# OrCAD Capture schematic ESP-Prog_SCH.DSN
size A3; title: ESP32-PROG-BRD_V2; rev: 1.0
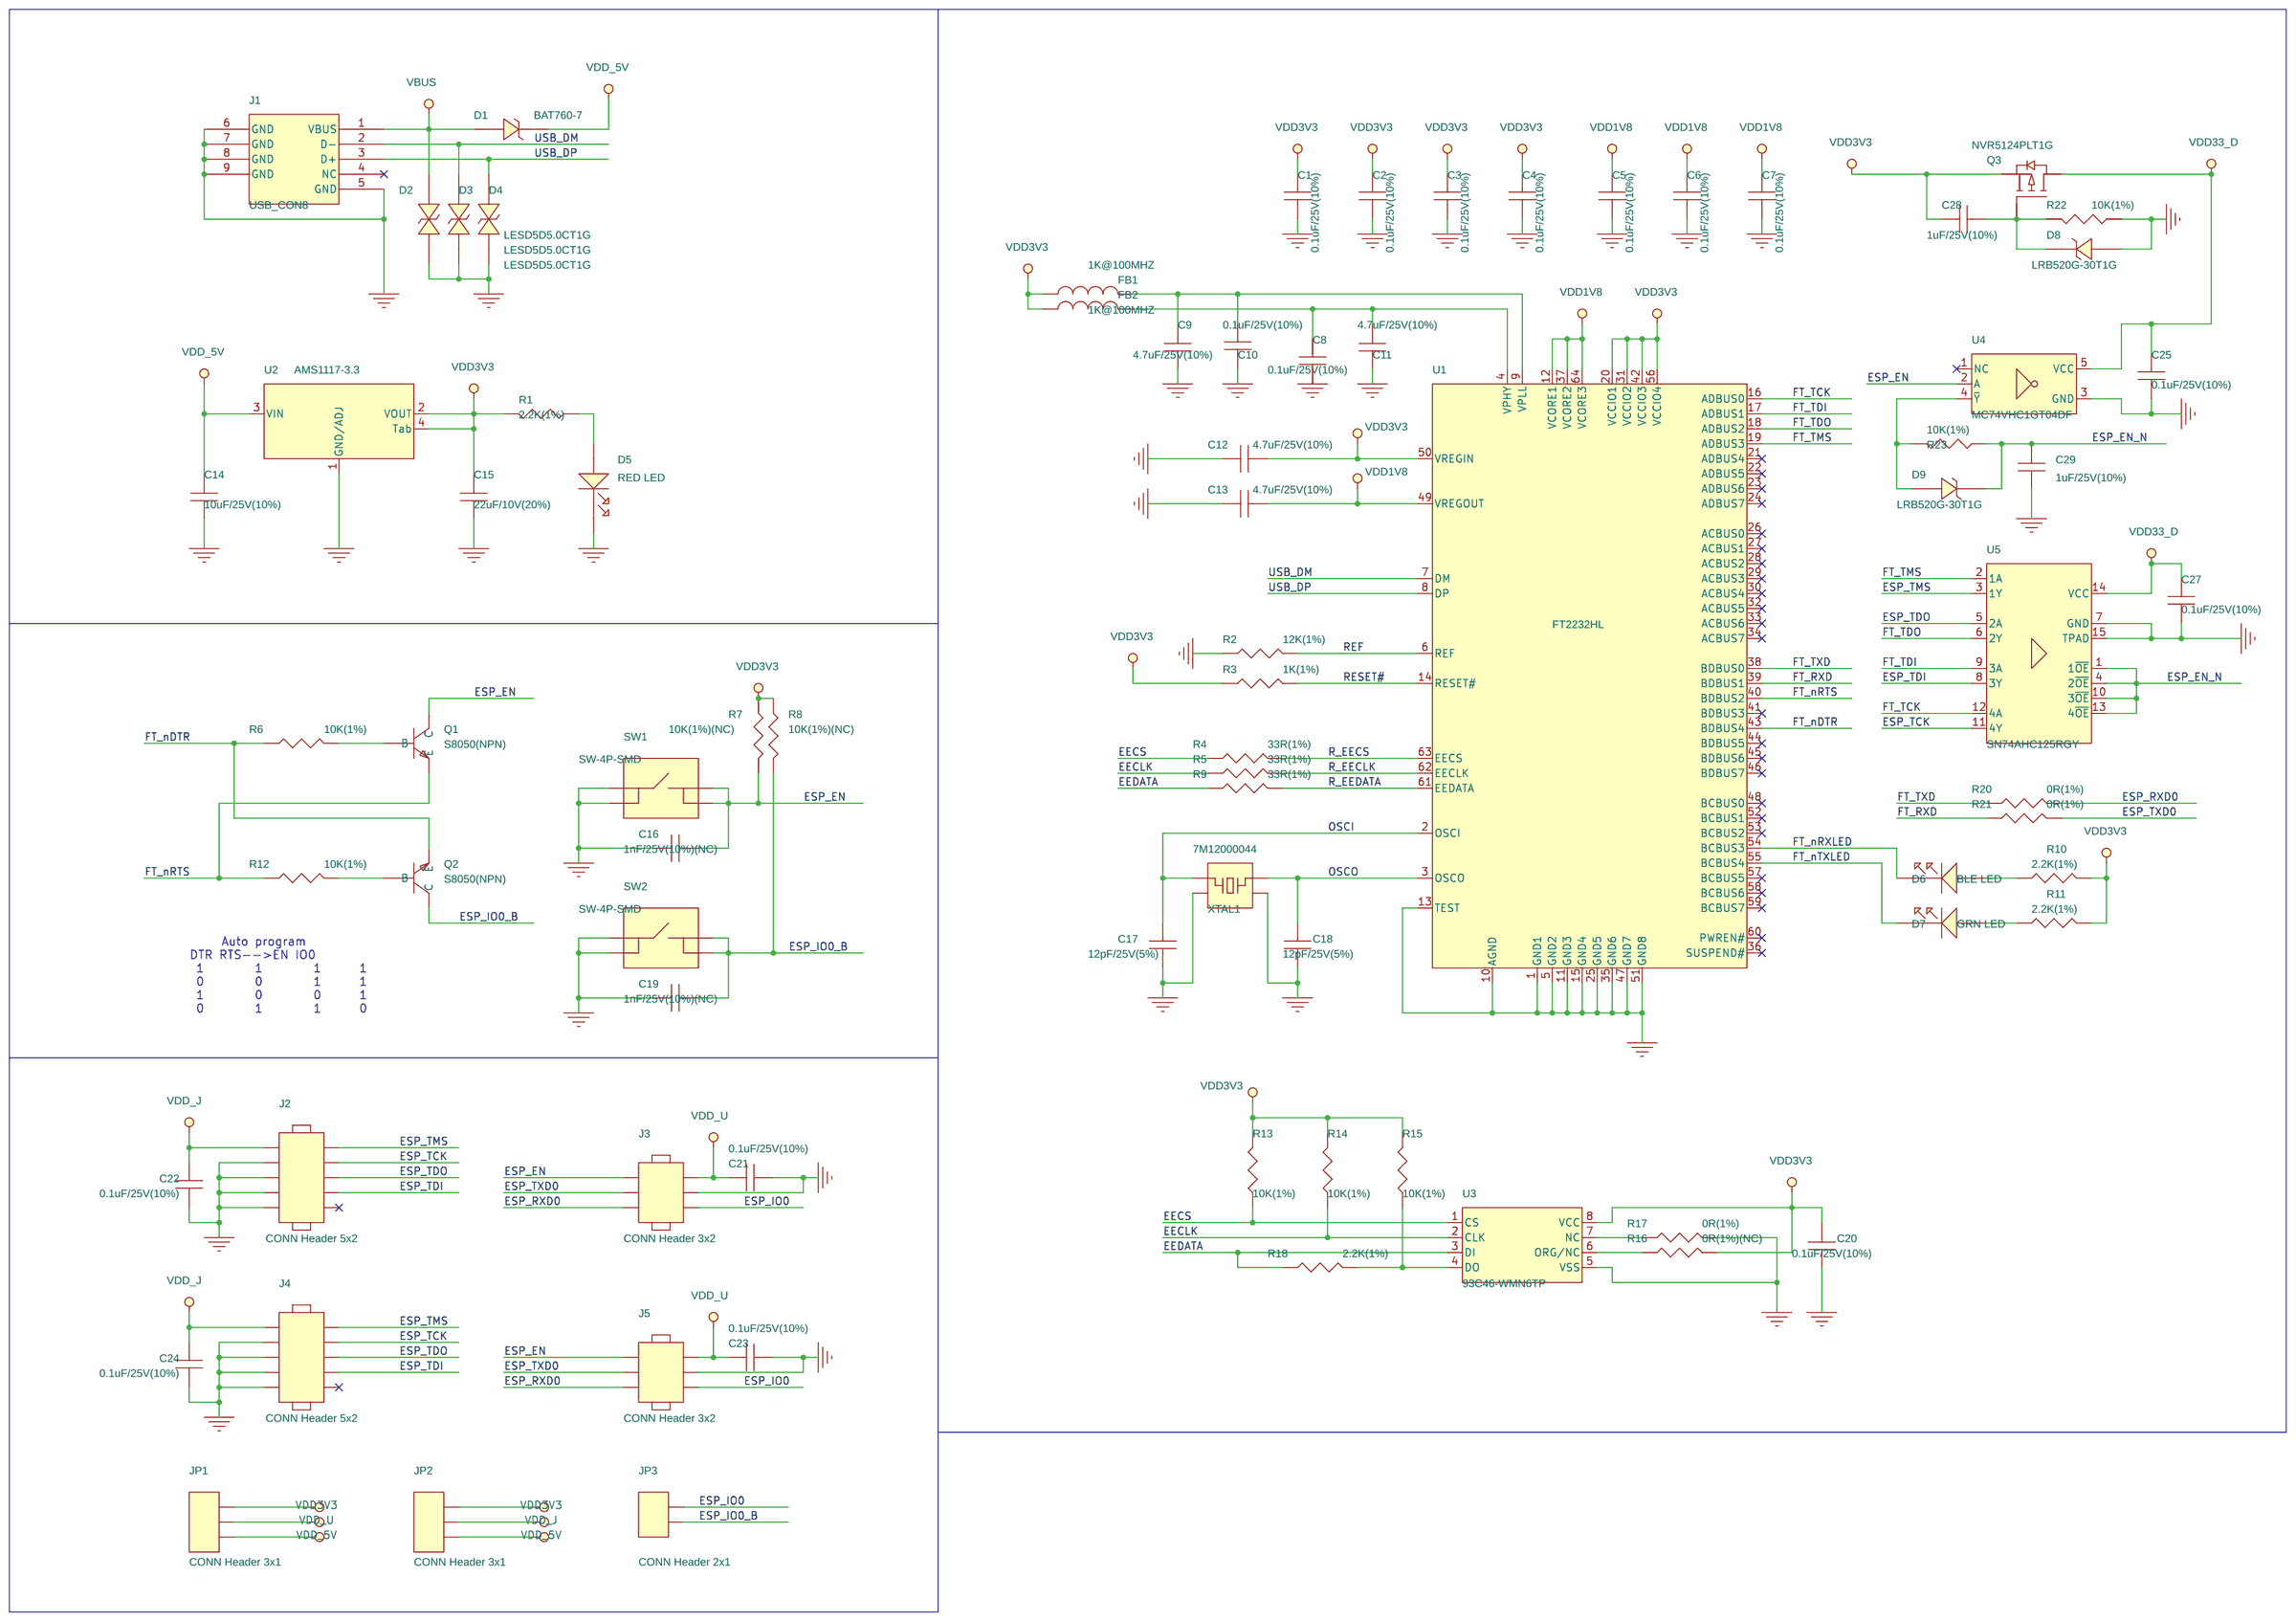
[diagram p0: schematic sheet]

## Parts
C1  0.1uF/25V(10%)  [0402C]
C2  0.1uF/25V(10%)  [0402C]
C3  0.1uF/25V(10%)  [0402C]
C4  0.1uF/25V(10%)  [0402C]
C5  0.1uF/25V(10%)  [0402C]
C6  0.1uF/25V(10%)  [0402C]
C7  0.1uF/25V(10%)  [0402C]
C8  0.1uF/25V(10%)  [0402C]
C9  4.7uF/25V(10%)  [0402C]
C10  0.1uF/25V(10%)  [0402C]
C11  4.7uF/25V(10%)  [0402C]
C12  4.7uF/25V(10%)  [0402C]
C13  4.7uF/25V(10%)  [0402C]
C14  10uF/25V(10%)  [0603C]
C15  22uF/10V(20%)  [0603C]
C16  1nF/25V(10%)(NC)  [0402C]
C17  12pF/25V(5%)  [0402C]
C18  12pF/25V(5%)  [0402C]
C19  1nF/25V(10%)(NC)  [0402C]
C20  0.1uF/25V(10%)  [0402C]
C21  0.1uF/25V(10%)  [0402C]
C22  0.1uF/25V(10%)  [0402C]
C23  0.1uF/25V(10%)  [0402C]
C24  0.1uF/25V(10%)  [0402C]
C25  0.1uF/25V(10%)  [0402C]
C27  0.1uF/25V(10%)  [0402C]
C28  1uF/25V(10%)  [0603C]
C29  1uF/25V(10%)  [0603C]
D1  BAT760-7  [SOD-323]
D2  LESD5D5.0CT1G  [SOD-523]
D3  LESD5D5.0CT1G  [SOD-523]
D4  LESD5D5.0CT1G  [SOD-523]
D5  RED LED  [0603D/A]
D6  BLE LED  [0603D/A]
D7  GRN LED  [0603D/A]
D8  LRB520G-30T1G  [D0402]
D9  LRB520G-30T1G  [D0402]
FB1  1K@100MHZ  [0603R]
FB2  1K@100MHZ  [0603R]
J1  USB_CON8  [USB_5P]
J2  CONN Header 5x2  [DC3-10P-1P27]
J3  CONN Header 3x2  [DC3-6P-1P27]
J4  CONN Header 5x2  [DC3-10P-2P54]
J5  CONN Header 3x2  [DC3-6P-2P54]
JP1  CONN Header 3x1  [CON_3X1_2P54]
JP2  CONN Header 3x1  [CON_3X1_2P54]
JP3  CONN Header 2x1  [CON_2X1_2P54]
Q1  S8050(NPN)  [SOT-23-3]
Q2  S8050(NPN)  [SOT-23-3]
Q3  NVR5124PLT1G  [SOT-23-3]
R1  2.2K(1%)  [0402R]
R2  12K(1%)  [0402R]
R3  1K(1%)  [0402R]
R4  33R(1%)  [0402R]
R5  33R(1%)  [0402R]
R6  10K(1%)  [0402R]
R7  10K(1%)(NC)  [0402R]
R8  10K(1%)(NC)  [0402R]
R9  33R(1%)  [0402R]
R10  2.2K(1%)  [0402R]
R11  2.2K(1%)  [0402R]
R12  10K(1%)  [0402R]
R13  10K(1%)  [0402R]
R14  10K(1%)  [0402R]
R15  10K(1%)  [0402R]
R16  0R(1%)(NC)  [0402R]
R17  0R(1%)  [0402R]
R18  2.2K(1%)  [0402R]
R20  0R(1%)  [0402R]
R21  0R(1%)  [0402R]
R22  10K(1%)  [0402R]
R23  10K(1%)  [0402R]
SW1  SW-4P-SMD  [BTN4-4P5X4P5X4P3]
SW2  SW-4P-SMD  [BTN4-4P5X4P5X4P3]
U1  FT2232HL  [LQFN64-0P5]
U2  AMS1117-3.3  [SOT-223]
U3  93C46-WMN6TP  [SOIC-8P]
U4  MC74VHC1GT04DF  [SOT-353]
U5  SN74AHC125RGY  [VQFN14-3P5X3P5]
XTAL1  7M12000044  [XTAL3225]

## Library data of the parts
C1-C25 C27-C29 = CAP_NP
D1 = DIODE_POWER
D2-D4 = DIODE_BI-DIR_TRIG
D5 D7 = LED_1
D6 = LED_0
D8 D9 = DIODE_POWER_1
FB1 FB2 = INDUCTOR
J1 = CON4_2
J2 J4 = 12_HEADER_1
J3 J5 = 12_HEADER_0
JP1 JP2 = CON1X4_2
JP3 = CON1X4_3
Q1 Q2 = NPN_BCE_3
Q3 = MOSFET_EN_DGS_1
R1-R18 R20-R23 = RESISTOR_0
SW1 SW2 = SW_0
U1 = FT2232HL_1
U2 = NCP1117_0
U3 = 93c46_0
U4 = 93c46_1
U5 = 93c46_4
XTAL1 = XTAL-HALF_0

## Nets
GND: C1.2 C2.2 C3.2 C4.2 C5.2 C6.2 C7.2 C8.2 C9.1 C10.2 C11.1 C12.1 C13.1 C14.1 C15.1 C16.1 C17.2 C18.2 C19.1 C20.1 C21.2 C22.2 C23.2 C24.2 C25.2 C27.2 C29.1 D2.2 D3.2 D4.2 D5.2(CATHODE) D8.2 J1.5(GND) J1.6(GND) J1.7(GND) J1.8(GND) J1.9(GND) J2.3 J2.5 J2.7 J2.9 J3.4 J4.3 J4.5 J4.7 J4.9 J5.4 R2.1 R17.2 R22.1 SW1.1 SW1.2 SW2.1 SW2.2 U1.1(GND1) U1.5(GND2) U1.10(AGND) U1.11(GND3) U1.13(TEST) U1.15(GND4) U1.25(GND5) U1.35(GND6) U1.47(GND7) U1.51(GND8) U2.1(GND/ADJ) U3.5(VSS) U4.3(GND) U5.7(GND) U5.15(TPAD) XTAL1.2 XTAL1.4
VBUS: D1.2 D2.1 J1.1(VBUS)
VDD1V8: C5.1 C6.1 C7.1 C13.2 U1.12(VCORE1) U1.37(VCORE2) U1.49(VREGOUT) U1.64(VCORE3)
VDD3V3: C1.1 C2.1 C3.1 C4.1 C12.2 C15.2 C20.2 C28.1 FB1.2 FB2.2 JP1.3 JP2.3 Q3.2(S) R1.1 R3.1 R7.1 R8.1 R10.2 R11.2 R13.2 R14.2 R15.2 R16.2 U1.20(VCCIO1) U1.31(VCCIO2) U1.42(VCCIO3) U1.50(VREGIN) U1.56(VCCIO4) U2.2(VOUT) U2.4(Tab) U3.8(VCC)
VDD33_D: C25.1 C27.1 Q3.3(D) U4.5(VCC) U5.14(VCC)
VDD_5V: C14.2 D1.1 JP1.1 JP2.1 U2.3(VIN)
VDD_J: C22.1 C24.1 J2.1 J4.1 JP2.2
VDD_U: C21.1 C23.1 J3.2 J5.2 JP1.2
EECLK: R5.1 R14.1 U3.2(CLK)
EECS: R4.1 R13.1 U3.1(CS)
EEDATA: R9.1 R18.1 U3.3(DI)
ESP_EN: C16.2 J3.1 J5.1 Q1.3(C) R7.2 SW1.3 SW1.4 U4.2(A)
ESP_EN_N: C29.2 D9.1 R23.1 U5.1(1~{OE}) U5.4(2~{OE}) U5.10(3~{OE}) U5.13(4~{OE})
ESP_IO0: J3.6 J5.6 JP3.2
ESP_IO0_B: C19.2 JP3.1 Q2.3(C) R8.2 SW2.3 SW2.4
ESP_RXD0: J3.5 J5.5 R20.2
ESP_TCK: J2.4 J4.4 U5.11(4Y)
ESP_TDI: J2.8 J4.8 U5.8(3Y)
ESP_TDO: J2.6 J4.6 U5.5(2A)
ESP_TMS: J2.2 J4.2 U5.3(1Y)
ESP_TXD0: J3.3 J5.3 R21.2
FT_nDTR: Q2.2(E) R6.1 U1.43(BDBUS4)
FT_nRTS: Q1.2(E) R12.1 U1.40(BDBUS2)
FT_nRXLED: D6.2(CATHODE) U1.54(BCBUS3)
FT_nTXLED: D7.2(CATHODE) U1.55(BCBUS4)
FT_RXD: R21.1 U1.39(BDBUS1)
FT_TCK: U1.16(ADBUS0) U5.12(4A)
FT_TDI: U1.17(ADBUS1) U5.9(3A)
FT_TDO: U1.18(ADBUS2) U5.6(2Y)
FT_TMS: U1.19(ADBUS3) U5.2(1A)
FT_TXD: R20.1 U1.38(BDBUS0)
OSCI: C17.1 U1.2(OSCI) XTAL1.1
OSCO: C18.1 U1.3(OSCO) XTAL1.3
R_EECLK: R5.2 U1.62(EECLK)
R_EECS: R4.2 U1.63(EECS)
R_EEDATA: R9.2 U1.61(EEDATA)
REF: R2.2 U1.6(REF)
RESET#: R3.2 U1.14(RESET#)
USB_DM: D3.1 J1.2(D-) U1.7(DM)
USB_DP: D4.1 J1.3(D+) U1.8(DP)
N16608660: R16.1 U3.6(ORG/NC)
N16608760: R15.1 R18.2 U3.4(DO)
N16615513: C9.2 C10.1 FB1.1 U1.9(VPLL)
N16615522: C8.1 C11.2 FB2.1 U1.4(VPHY)
N16719737: Q1.1(B) R6.2
N16719809: Q2.1(B) R12.2
N16734611: D6.1(ANODE) R10.1
N16734691: D7.1(ANODE) R11.1
N16864027: R17.1 U3.7(NC)
N17074653: D5.1(ANODE) R1.2
N17135421: C28.2 D8.1 Q3.1(G) R22.2
N17139144: D9.2 R23.2 U4.4(~{Y})

Not connected (* = marked no-connect by the designer): J1 4(NC)*; J2 10*; J4 10*; U1 21(ADBUS4)* 22(ADBUS5)* 23(ADBUS6)* 24(ADBUS7)* 26(ACBUS0)* 27(ACBUS1)* 28(ACBUS2)* 29(ACBUS3)* 30(ACBUS4)* 32(ACBUS5)* 33(ACBUS6)* 34(ACBUS7)* 36(SUSPEND#)* 41(BDBUS3)* 44(BDBUS5)* 45(BDBUS6)* 46(BDBUS7)* 48(BCBUS0)* 52(BCBUS1)* 53(BCBUS2)* 57(BCBUS5)* 58(BCBUS6)* 59(BCBUS7)* 60(PWREN#)*; U4 1(NC)*

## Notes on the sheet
- Auto program
  DTR RTS-->EN IO0
   1        1        1      1
   0        0        1      1
   1        0        0      1
   0        1        1      0
